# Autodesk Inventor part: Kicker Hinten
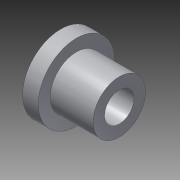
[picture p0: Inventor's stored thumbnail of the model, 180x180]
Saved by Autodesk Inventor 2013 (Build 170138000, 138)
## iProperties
Created: 2012-07
Part Number: Kicker Hinten
Material: Aluminium 6061
Document SubType Name: Modeling
Designer: rYan
Mass: 2.80629 g
Surface Area: 10.3218 cm^2
Volume: 1.03553 cm^3
Density: 2.71 g/cm^3
Author: rYan
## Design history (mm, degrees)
sketch "Skizze1"
  geometry: L1 (-6.15, 0)-(-6.15, 8); L2 (-6.15, 8)-(-2.85, 8); L3 (-2.85, 8)-(-2.85, 5.5); L4 (-2.85, 5.5)-(6.15, 5.5); L5 (6.15, 5.5)-(6.15, 0); L6 (6.15, 0)-(-6.15, 0); L7 (0, 9.6)-(0, -1.6) reference; L8 (-8.61, 0)-(8.61, 0) reference; 1 further point
  constraints: 12 end point, 3 perpendicular, 2 parallel, 1 collinear, 1 vertical, 1 other
  dimensions: "d1" = 3.3 distance of L1.end L2.end; "d3" = 9 distance of L3.end L4.end; "d4" = 11 diameter of L4 L6; "d5" = 16 diameter of L2 L6
revolve "Umdrehung1" sketch "Skizze1" stored, may be unused: angle "d6" = 90 deg
sketch "Skizze2"
  geometry: C1 r 8 at (0, 0) reference; 2 further points
  constraints: 1 coincident
hole "Bohrung1" sketch "Skizze2" at (0, 0) diameter "d7" = 6.2; stored, may be unused: countersink angle "d11" = 90 deg, drill point angle "d13" = 118 deg; dims "d8" = 6, "d9" = 13, "d10" = 2, "d12" = 8
node "Volumenkörper1"
